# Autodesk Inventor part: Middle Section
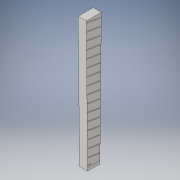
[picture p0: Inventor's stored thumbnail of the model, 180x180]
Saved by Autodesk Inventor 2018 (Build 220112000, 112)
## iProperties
Created: 2018-10
Part Number: Middle Section
Material: Generic
Document SubType Name: Modeling
Designer: johne
Density: 1 g/cm^3
Appearance: Default
Author: johne
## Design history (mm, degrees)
sketch "Sketch1"
  geometry: L1 (0, 0)-(25.4, 0); L2 (25.4, 0)-(25.4, -76.2); L3 (25.4, -76.2)-(0, -76.2); L4 (0, -76.2)-(0, 0)
  constraints: 8 end point, 2 parallel, 1 horizontal, 1 perpendicular
  dimensions: "d0" = 25.4 distance of L2.end L3.end; "d1" = 76.2 distance of L1.end L2.end
extrude "Extrusion1" new body sketch "Sketch1" distance "d2" = 25.4; taper "d3" = 0 deg
sketch "Sketch3"
  geometry: L1 (-2.627, -64.34)-(-23.226, -64.34); L2 (-23.226, -64.34)-(-23.226, -10.419); L3 (-23.226, -10.419)-(-2.627, -10.419); L4 (-2.627, -10.419)-(-2.627, -64.34); 1 further point
  constraints: 8 end point, 2 parallel, 1 horizontal, 1 perpendicular
extrude "Extrusion2" join sketch "Sketch3" distance "d4" = 25.4; taper "d5" = 0 deg
sketch "Sketch4"
  geometry: L1 (9.188, -40.142)-(9.188, 0); L2 (65.781, 0)-(-10.419, 0) reference; L3 (49.65, -33.733)-(49.65, 0); L4 (49.65, -33.733)-(75.988, -33.733); L5 (75.988, -33.733)-(75.988, 0); L6 (75.988, 0)-(49.65, 0); L7 (49.65, 0)-(49.65, -33.733); L8 (9.188, 0)-(-27.007, 0); L9 (-27.007, 0)-(-27.007, -40.142); L10 (-27.007, -40.142)-(9.188, -40.142); L11 (9.188, -40.142)-(9.188, 0); A1 r 0.762 centre (49.65, -33.733) between (49.77, -34.486) and (49.531, -32.981) reference; A2 r 0.762 centre (9.188, -40.142) between (9.846, -39.758) and (8.53, -40.527) reference; 1 further point
  constraints: 20 end point, 4 parallel, 3 perpendicular, 2 horizontal, 2 point on circle, 2 point on line, 1 centre point, 1 vertical, 4 other
extrude "Extrusion3" cut sketch "Sketch4" distance "d6" = 25.4; taper "d7" = 0 deg
sketch "Sketch5"
  geometry: L1 (17.911, -0.752)-(29.845, -0.752); L2 (29.845, -0.752)-(29.845, 25.4); L3 (29.845, 25.4)-(17.911, 25.4); L4 (17.911, 25.4)-(17.911, -0.752); L5 (2.925, -7.161)-(-11.223, -7.161); L6 (-11.223, -7.161)-(-11.223, 25.4); L7 (-11.223, 25.4)-(2.925, 25.4); L8 (2.925, 25.4)-(2.925, -7.161); 5 further points; 2 other entities
  constraints: 16 end point, 4 parallel, 2 horizontal, 2 perpendicular, 1 point on line, 2 other
extrude "Extrusion4" cut sketch "Sketch5" distance "d8" = 76.2; taper "d9" = 0 deg
sketch "Sketch6"
  geometry: L1 (-20.538, -19.607)-(-20.538, -60.069) reference; L2 (-20.538, -26.89)-(-20.538, -19.607); L3 (-20.538, -19.607)-(-13.045, -19.607); A1 r 7.62 centre (-12.926, -27.226) between (-13.045, -19.607) and (-20.538, -26.89); 1 further point
  constraints: 4 end point, 2 point on circle, 1 centre point, 1 collinear, 1 perpendicular, 2 other
  dimensions: "d10" = 7.62 radius of A1
extrude "Extrusion5" cut sketch "Sketch6" stored distance "d11" = 76.2; taper "d12" = 0 deg
workplane "Work Plane1"
workplane "Work Plane2"
mirror "Mirror1"
mirror "Mirror2"
sketch "Sketch7"
  geometry: L1 (-5.552, -52.785)-(-5.552, -26.89) reference; L2 (-20.538, -26.89)-(-20.538, -52.785) reference; A1 r 7.62 centre (-13.165, -52.45) between (-13.045, -60.069) and (-5.552, -52.785) reference; A2 r 7.62 centre (-13.165, -27.226) between (-5.552, -26.89) and (-13.045, -19.607) reference; A3 r 7.62 centre (-12.926, -27.226) between (-13.045, -19.607) and (-20.538, -26.89) reference; A4 r 7.62 centre (-12.926, -52.45) between (-20.538, -52.785) and (-13.045, -60.069) reference; 1 further point
extrude "Extrusion6" join sketch "Sketch7" distance "d13" = 184.15; taper "d14" = 0 deg
feature "Sculpt1"
sketch "Sketch8"
  geometry: C1 r 0.762 at (0, 0) reference; 1 further point
extrude "Extrusion7" cut sketch "Sketch8" distance "d15" = 184.15; taper "d16" = 0 deg
sketch "Sketch10"
  geometry: L1 (56.593, -27.851)-(56.593, -39.145) reference; L2 (49.31, -25.4)-(56.593, -25.4) reference; L3 (56.593, -25.4)-(62.943, -25.4); L4 (76.2, -25.4)-(0, -25.4) reference; L5 (23.415, -25.4)-(16.131, -25.4) reference; L6 (16.131, -25.4)-(9.781, -25.4); L7 (9.781, -25.4)-(-4.173, -25.4); L8 (-4.173, -25.4)-(-4.173, 6.216); L9 (-4.173, 6.216)-(9.781, 6.216); L10 (9.781, 6.216)-(9.781, -25.4); L11 (62.943, -25.4)-(76.826, -25.4); L12 (76.826, -25.4)-(76.826, 0); L13 (76.826, 0)-(62.943, 0); L14 (62.943, 0)-(62.943, -25.4); 3 further points; 1 other entity
  constraints: 20 end point, 4 parallel, 2 horizontal, 2 perpendicular, 2 point on line, 1 coincident
  dimensions: "d19" = 6.35 distance of L2.end L3.end; "d20" = 6.35 distance of L5.end L6.end
extrude "Extrusion9" cut sketch "Sketch10" distance "d21" = 50.8; taper "d22" = 0 deg
sketch "Sketch11"
  geometry: L1 (0, -25.4)-(53.163, -25.4) reference; L2 (53.163, -25.4)-(53.163, -12.7); L3 (53.163, 0)-(53.163, -25.4) reference; L4 (-7.051, -12.7)-(-7.051, 2.628); L5 (-7.051, 2.628)-(53.163, 2.628); L6 (53.163, 2.628)-(53.163, -12.7); L7 (-7.051, -12.7)-(-7.051, -25.4); L8 (-7.051, -25.4)-(53.163, -25.4); 1 further point
  constraints: 12 end point, 1 midpoint, 1 parallel, 1 perpendicular, 1 vertical
extrude "Extrusion10" cut sketch "Sketch11" distance "d23" = 50.8; taper "d24" = 0 deg
sketch "Sketch14"
  geometry: L1 (-14.986, 25.895)-(-14.986, 0) reference; L2 (0, 0)-(0, 25.895) reference; L3 (-0.375, 25.887)-(-0.375, 0.008); L4 (-14.612, 0.008)-(-14.612, 25.887); A1 r 7.62 centre (-7.613, 25.56) between (0, 25.895) and (-7.493, 33.179) reference; A2 r 7.62 centre (-7.374, 25.56) between (-7.493, 33.179) and (-14.986, 25.895) reference; A3 r 7.62 centre (-7.613, 0.335) between (-7.493, -7.284) and (0, 0) reference; A4 r 7.62 centre (-7.374, 0.335) between (-14.986, 0) and (-7.493, -7.284) reference; A5 r 7.245 centre (-7.613, 25.56) between (-0.375, 25.887) and (-7.493, 32.804); A6 r 7.245 centre (-7.613, 0.335) between (-7.493, -6.909) and (-0.375, 0.008); A7 r 7.245 centre (-7.374, 0.335) between (-14.612, 0.008) and (-7.493, -6.909); A8 r 7.245 centre (-7.374, 25.56) between (-7.493, 32.804) and (-14.612, 25.887); 1 further point
  constraints: 8 point on circle, 4 centre point, 4 end point, 5 other
  dimensions: "d36" = 0.37465 radial gap between concentric circles of A1 A5
extrude "Extrusion13" cut sketch "Sketch14" distance "d37" = 300; taper "d38" = 0 deg
sketch "Sketch15"
  geometry: L1 (-20.164, -26.899)-(-20.164, -52.777) reference; L2 (-5.927, -52.777)-(-5.927, -26.899) reference; L3 (-19.976, -52.773)-(-19.976, -26.903); L4 (-6.114, -26.903)-(-6.114, -52.773); A1 r 7.245 centre (-12.926, -27.226) between (-13.045, -19.981) and (-20.164, -26.899) reference; A2 r 7.245 centre (-12.926, -52.45) between (-20.164, -52.777) and (-13.045, -59.694) reference; A3 r 7.245 centre (-13.165, -52.45) between (-13.045, -59.694) and (-5.927, -52.777) reference; A4 r 7.245 centre (-13.165, -27.226) between (-5.927, -26.899) and (-13.045, -19.981) reference; A5 r 7.058 centre (-12.926, -27.226) between (-13.045, -20.169) and (-19.976, -26.903); A6 r 7.058 centre (-13.165, -27.226) between (-6.114, -26.903) and (-13.045, -20.169); A7 r 7.058 centre (-13.165, -52.45) between (-13.045, -59.507) and (-6.114, -52.773); A8 r 7.058 centre (-12.926, -52.45) between (-19.976, -52.773) and (-13.045, -59.507); 1 further point
  constraints: 8 point on circle, 4 centre point, 4 end point, 5 other
  dimensions: "d39" = 0.18733 distance between parallel lines of L1 L3
loft "Loft1" sketch "Sketch15" dims "d40" = 0, "d41" = 90 deg, "d42" = 0, "d43" = 90 deg
  node "Edges1"
node "Direct Edit2"
sketch "Sketch18"
  geometry: L1 (0, 0)-(0, 24.576) reference; L2 (13.169, 24.576)-(13.169, 0) reference; 3 further points
  constraints: 4 other
extrude "Extrusion16" join sketch "Sketch18" distance "d52" = 5; taper "d53" = 0 deg
workplane "Work Plane3"
sketch "Sketch22"
  geometry: L1 (-54.51, -262.283)-(48.253, -262.283); L2 (48.253, -262.283)-(48.253, 26.465); L3 (48.253, 26.465)-(-54.51, 26.465); L4 (-54.51, 26.465)-(-54.51, -262.283); 1 further point
  constraints: 8 end point, 2 parallel, 1 horizontal, 1 perpendicular
extrude "Extrusion18" cut sketch "Sketch22" distance "d63" = 300; taper "d64" = 0 deg
workplane "Work Plane5"
  workplane "Work Plane4"
mirror "Mirror3"
body "Solid1"
node "Reference1"
node "Reference2"
node "Reference3"
node "Projected Loop1"
node "Projected Loop2"
node "Projected Loop3"
feature "Composite1"
body "Srf1"
feature "Scale2"
other parameters: "d45" = 9.5, "d46" = 9.5, "d65" = 90 deg
